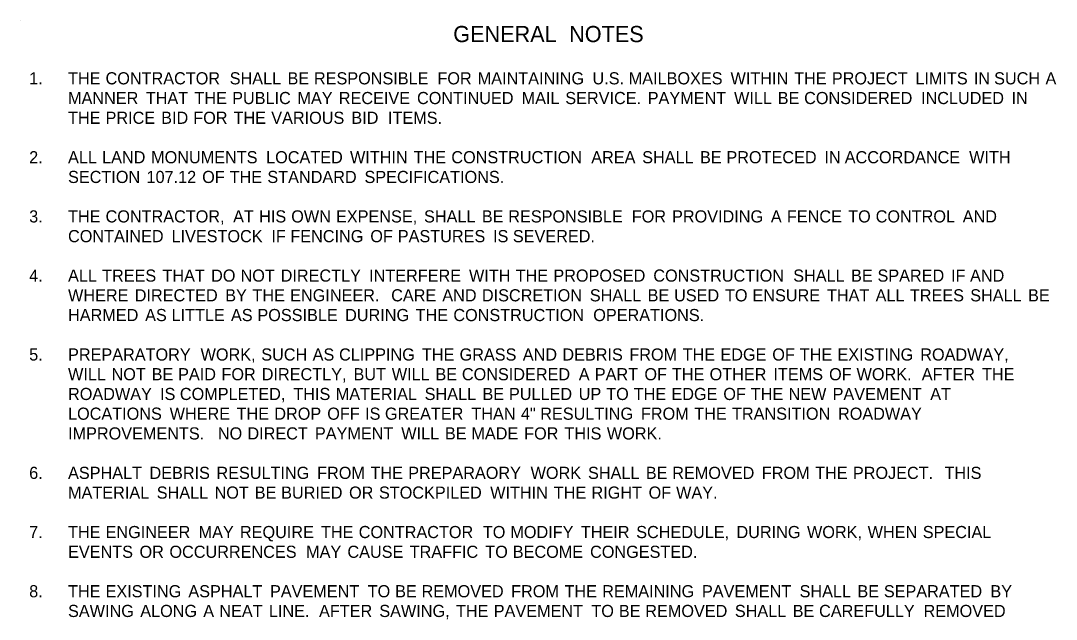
# Model space of a CAD drawing. Extents: x 1930579 to 1932219, y 596452 to 599493.
# Drawn here: x 1930766 to 1931329, y 599100 to 599425 of the extents above; entities that cross this region are included whole.
import ezdxf

# ---------------------------------------------------------------- set-up
doc = ezdxf.new("R2010")
doc.units = 0
doc.layers.add('Default', color=7, linetype='Continuous')
doc.layers.add('R_Border', color=7, linetype='Continuous')

msp = doc.modelspace()

# ---------------------------------------------------------------- linework, layer by layer
at = {"layer": 'R_Border'}
msp.add_line((1930766.07, 599425.04), (1930766.07, 599425.04), dxfattribs=at)

# ---------------------------------------------------------------- texts
at = {"layer": 'Default'}
for s, height, p in [('GENERAL', 8.8, (1931001.3, 599413.4)), (' NOTES', 8.8, (1931061.06, 599413.4)), ('1.', 6.6, (1930770.67, 599390.43)), ('THE', 6.6, (1930791.81, 599390.43)), (' CONTRACTOR', 6.6, (1930809.76, 599390.43)), (' SHALL', 6.6, (1930877.27, 599390.43)), (' BE', 6.6, (1930908.72, 599390.43)), (' RESPONSIBLE', 6.6, (1930923.09, 599390.43)), (' FOR', 6.6, (1930990.25, 599390.43)), (' MAINTAINING', 6.6, (1931012.15, 599390.43)), (' U.S.', 6.6, (1931074.59, 599390.43)), (' MAILBOXES', 6.6, (1931094.28, 599390.43)), (' WITHIN', 6.6, (1931149.66, 599390.43)), (' THE', 6.6, (1931184.25, 599390.43)), (' PROJECT', 6.6, (1931204.76, 599390.43)), (' LIMITS', 6.6, (1931250.18, 599390.43)), (' IN', 6.6, (1931281.97, 599390.43)), (' SUCH', 6.6, (1931293, 599390.43)), (' A', 6.6, (1931320.95, 599390.43)), ('MANNER', 6.6, (1930791.81, 599379.71)), (' THAT', 6.6, (1930831.65, 599379.71)), (' THE', 6.6, (1930858.1, 599379.71)), (' PUBLIC', 6.6, (1930878.62, 599379.71)), (' MAY', 6.6, (1930914.12, 599379.71)), (' RECEIVE', 6.6, (1930936.6, 599379.71)), (' CONTINUED', 6.6, (1930979.16, 599379.71)), (' MAIL', 6.6, (1931036.05, 599379.71)), (' SERVICE.', 6.6, (1931059.8, 599379.71)), (' PAYMENT', 6.6, (1931104.61, 599379.71)), (' WILL', 6.6, (1931151.57, 599379.71)), (' BE', 6.6, (1931175.32, 599379.71)), (' CONSIDERED', 6.6, (1931189.69, 599379.71)), (' INCLUDED', 6.6, (1931253.25, 599379.71)), (' IN', 6.6, (1931302.46, 599379.71)), ('THE', 6.6, (1930791.81, 599368.98)), (' PRICE', 6.6, (1930809.76, 599368.98)), (' BID', 6.6, (1930840.01, 599368.98)), (' FOR', 6.6, (1930857.46, 599368.98)), (' THE', 6.6, (1930879.36, 599368.98)), (' VARIOUS', 6.6, (1930899.87, 599368.98)), (' BID', 6.6, (1930943.46, 599368.98)), ('  ITEMS.', 6.6, (1930960.9, 599368.98)), ('2.', 6.6, (1930770.67, 599347.53)), ('ALL', 6.6, (1930791.81, 599347.53)), (' LAND', 6.6, (1930807.88, 599347.53)), (' MONUMENTS', 6.6, (1930834.55, 599347.53)), (' LOCATED', 6.6, (1930897.09, 599347.53)), (' WITHIN', 6.6, (1930942.71, 599347.53)), (' THE', 6.6, (1930977.3, 599347.53)), (' CONSTRUCTION', 6.6, (1930997.81, 599347.53)), (' AREA', 6.6, (1931073.91, 599347.53)), (' SHALL', 6.6, (1931101.6, 599347.53)), (' BE', 6.6, (1931133.05, 599347.53)), (' PROTECED', 6.6, (1931147.42, 599347.53)), (' IN', 6.6, (1931200.74, 599347.53)), (' ACCORDANCE', 6.6, (1931211.76, 599347.53)), (' WITH', 6.6, (1931279.42, 599347.53)), ('SECTION', 6.6, (1930791.81, 599336.81)), (' 107.12', 6.6, (1930832.05, 599336.81)), (' OF', 6.6, (1930862.31, 599336.81)), (' THE', 6.6, (1930877.26, 599336.81)), (' STANDARD', 6.6, (1930897.77, 599336.81)), (' SPECIFICATIONS.', 6.6, (1930950.57, 599336.81)), ('3.', 6.6, (1930770.67, 599315.36)), ('THE', 6.6, (1930791.81, 599315.36)), (' CONTRACTOR,', 6.6, (1930809.76, 599315.36)), (' AT', 6.6, (1930879.13, 599315.36)), (' HIS', 6.6, (1930893.29, 599315.36)), (' OWN', 6.6, (1930910.74, 599315.36)), (' EXPENSE,', 6.6, (1930935.09, 599315.36)), (' SHALL', 6.6, (1930982.96, 599315.36)), (' BE', 6.6, (1931014.41, 599315.36)), (' RESPONSIBLE', 6.6, (1931028.78, 599315.36)), (' FOR', 6.6, (1931095.95, 599315.36)), (' PROVIDING', 6.6, (1931117.85, 599315.36)), (' A', 6.6, (1931171.58, 599315.36)), (' FENCE', 6.6, (1931180.31, 599315.36)), (' TO', 6.6, (1931213.64, 599315.36)), (' CONTROL', 6.6, (1931228.59, 599315.36)), (' AND', 6.6, (1931275.92, 599315.36)), ('CONTAINED', 6.6, (1930791.81, 599304.63)), (' LIVESTOCK', 6.6, (1930845.63, 599304.63)), (' IF', 6.6, (1930899.93, 599304.63)), (' FENCING', 6.6, (1930910.27, 599304.63)), (' OF', 6.6, (1930953.75, 599304.63)), (' PASTURES', 6.6, (1930968.69, 599304.63)), (' IS', 6.6, (1931020.49, 599304.63)), (' SEVERED.', 6.6, (1931031.28, 599304.63)), ('4.', 6.6, (1930770.67, 599283.18)), ('ALL', 6.6, (1930791.81, 599283.18)), (' TREES', 6.6, (1930807.88, 599283.18)), (' THAT', 6.6, (1930840.71, 599283.18)), (' DO', 6.6, (1930867.17, 599283.18)), (' NOT', 6.6, (1930883.15, 599283.18)), (' DIRECTLY', 6.6, (1930904.99, 599283.18)), (' INTERFERE', 6.6, (1930953.09, 599283.18)), (' WITH', 6.6, (1931007.42, 599283.18)), (' THE', 6.6, (1931032.8, 599283.18)), (' PROPOSED', 6.6, (1931053.31, 599283.18)), (' CONSTRUCTION', 6.6, (1931107.66, 599283.18)), (' SHALL', 6.6, (1931183.75, 599283.18)), (' BE', 6.6, (1931215.2, 599283.18)), (' SPARED', 6.6, (1931229.58, 599283.18)), (' IF', 6.6, (1931269.57, 599283.18)), (' AND', 6.6, (1931279.91, 599283.18)), ('WHERE', 6.6, (1930791.81, 599272.46)), (' DIRECTED', 6.6, (1930825.64, 599272.46)), (' BY', 6.6, (1930874.85, 599272.46)), (' THE', 6.6, (1930889.65, 599272.46)), (' ENGINEER.', 6.6, (1930910.16, 599272.46)), ('  CARE', 6.6, (1930962.65, 599272.46)), (' AND', 6.6, (1930992.9, 599272.46)), (' DISCRETION', 6.6, (1931014.44, 599272.46)), (' SHALL', 6.6, (1931073.12, 599272.46)), (' BE', 6.6, (1931104.57, 599272.46)), (' USED', 6.6, (1931118.95, 599272.46)), (' TO', 6.6, (1931146.64, 599272.46)), (' ENSURE', 6.6, (1931161.59, 599272.46)), (' THAT', 6.6, (1931202.1, 599272.46)), (' ALL', 6.6, (1931228.55, 599272.46)), (' TREES', 6.6, (1931247.19, 599272.46)), (' SHALL', 6.6, (1931280.02, 599272.46)), (' BE', 6.6, (1931311.47, 599272.46)), ('HARMED', 6.6, (1930791.81, 599261.73)), (' AS', 6.6, (1930831.28, 599261.73)), (' LITTLE', 6.6, (1930845.66, 599261.73)), (' AS', 6.6, (1930877.96, 599261.73)), (' POSSIBLE', 6.6, (1930892.35, 599261.73)), (' DURING', 6.6, (1930940.04, 599261.73)), (' THE', 6.6, (1930978.39, 599261.73)), (' CONSTRUCTION', 6.6, (1930998.91, 599261.73)), (' OPERATIONS.', 6.6, (1931075, 599261.73)), ('5.', 6.6, (1930770.67, 599240.28)), ('PREPARATORY', 6.6, (1930791.81, 599240.28)), (' WORK,', 6.6, (1930861.44, 599240.28)), (' SUCH', 6.6, (1930894.43, 599240.28)), (' AS', 6.6, (1930922.38, 599240.28)), (' CLIPPING', 6.6, (1930936.76, 599240.28)), (' THE', 6.6, (1930981.79, 599240.28)), (' GRASS', 6.6, (1931002.3, 599240.28)), (' AND', 6.6, (1931036.67, 599240.28)), (' DEBRIS', 6.6, (1931058.21, 599240.28)), (' FROM', 6.6, (1931094.63, 599240.28)), (' THE', 6.6, (1931123.64, 599240.28)), (' EDGE', 6.6, (1931144.16, 599240.28)), (' OF', 6.6, (1931172.36, 599240.28)), (' THE', 6.6, (1931187.31, 599240.28)), (' EXISTING', 6.6, (1931207.82, 599240.28)), (' ROADWAY,', 6.6, (1931252.85, 599240.28)), ('WILL', 6.6, (1930791.81, 599229.56)), (' NOT', 6.6, (1930813, 599229.56)), (' BE', 6.6, (1930834.84, 599229.56)), (' PAID', 6.6, (1930849.21, 599229.56)), (' FOR', 6.6, (1930872.8, 599229.56)), (' DIRECTLY,', 6.6, (1930894.71, 599229.56)), (' BUT', 6.6, (1930944.61, 599229.56)), (' WILL', 6.6, (1930965.43, 599229.56)), (' BE', 6.6, (1930989.18, 599229.56)), (' CONSIDERED', 6.6, (1931003.56, 599229.56)), (' A', 6.6, (1931067.12, 599229.56)), (' PART', 6.6, (1931075.84, 599229.56)), (' OF', 6.6, (1931102.82, 599229.56)), (' THE', 6.6, (1931117.76, 599229.56)), (' OTHER', 6.6, (1931138.28, 599229.56)), (' ITEMS', 6.6, (1931172.99, 599229.56)), (' OF', 6.6, (1931203.25, 599229.56)), (' WORK.', 6.6, (1931218.2, 599229.56)), ('  AFTER', 6.6, (1931251.2, 599229.56)), (' THE', 6.6, (1931286.43, 599229.56)), ('ROADWAY', 6.6, (1930791.81, 599218.83)), (' IS', 6.6, (1930839.39, 599218.83)), (' COMPLETED,', 6.6, (1930850.18, 599218.83)), (' THIS', 6.6, (1930911.88, 599218.83)), (' MATERIAL', 6.6, (1930934.96, 599218.83)), (' SHALL', 6.6, (1930983.31, 599218.83)), (' BE', 6.6, (1931014.76, 599218.83)), (' PULLED', 6.6, (1931029.14, 599218.83)), (' UP', 6.6, (1931067.08, 599218.83)), (' TO', 6.6, (1931082.05, 599218.83)), (' THE', 6.6, (1931097.01, 599218.83)), (' EDGE', 6.6, (1931117.52, 599218.83)), (' OF', 6.6, (1931145.73, 599218.83)), (' THE', 6.6, (1931160.67, 599218.83)), (' NEW', 6.6, (1931181.19, 599218.83)), (' PAVEMENT', 6.6, (1931205.16, 599218.83)), (' AT', 6.6, (1931258.27, 599218.83)), ('LOCATIONS', 6.6, (1930791.81, 599208.11)), (' WHERE', 6.6, (1930844.62, 599208.11)), (' THE', 6.6, (1930881.01, 599208.11)), (' DROP', 6.6, (1930901.53, 599208.11)), (' OFF', 6.6, (1930930.33, 599208.11)), (' IS', 6.6, (1930950.91, 599208.11)), (' GREATER', 6.6, (1930961.7, 599208.11)), (' THAN', 6.6, (1931008.72, 599208.11)), (' 4"', 6.6, (1931035.64, 599208.11)), (' RESULTING', 6.6, (1931046.16, 599208.11)), (' FROM', 6.6, (1931100.93, 599208.11)), (' THE', 6.6, (1931129.94, 599208.11)), (' TRANSITION', 6.6, (1931150.46, 599208.11)), (' ROADWAY', 6.6, (1931208.11, 599208.11)), ('IMPROVEMENTS.', 6.6, (1930791.81, 599197.38)), ('  NO', 6.6, (1930868.38, 599197.38)), (' DIRECT', 6.6, (1930886.92, 599197.38)), (' PAYMENT', 6.6, (1930923.62, 599197.38)), (' WILL', 6.6, (1930970.58, 599197.38)), (' BE', 6.6, (1930994.33, 599197.38)), (' MADE', 6.6, (1931008.7, 599197.38)), (' FOR', 6.6, (1931037.42, 599197.38)), (' THIS', 6.6, (1931059.32, 599197.38)), (' WORK.', 6.6, (1931082.4, 599197.38)), ('6.', 6.6, (1930770.67, 599175.93)), ('ASPHALT', 6.6, (1930791.81, 599175.93)), (' DEBRIS', 6.6, (1930833.65, 599175.93)), (' RESULTING', 6.6, (1930870.07, 599175.93)), (' FROM', 6.6, (1930924.83, 599175.93)), (' THE', 6.6, (1930953.84, 599175.93)), (' PREPARAORY', 6.6, (1930974.36, 599175.93)), (' WORK', 6.6, (1931040.92, 599175.93)), (' SHALL', 6.6, (1931072.15, 599175.93)), (' BE', 6.6, (1931103.6, 599175.93)), (' REMOVED', 6.6, (1931117.97, 599175.93)), (' FROM', 6.6, (1931166.67, 599175.93)), (' THE', 6.6, (1931195.69, 599175.93)), (' PROJECT.', 6.6, (1931216.2, 599175.93)), ('  THIS', 6.6, (1931263.56, 599175.93)), ('MATERIAL', 6.6, (1930791.81, 599165.21)), (' SHALL', 6.6, (1930837.6, 599165.21)), (' NOT', 6.6, (1930869.05, 599165.21)), (' BE', 6.6, (1930890.89, 599165.21)), (' BURIED', 6.6, (1930905.26, 599165.21)), (' OR', 6.6, (1930942.18, 599165.21)), (' STOCKPILED', 6.6, (1930958.45, 599165.21)), (' WITHIN', 6.6, (1931018.94, 599165.21)), (' THE', 6.6, (1931053.52, 599165.21)), (' RIGHT', 6.6, (1931074.04, 599165.21)), (' OF', 6.6, (1931105.1, 599165.21)), (' WAY.', 6.6, (1931120.05, 599165.21)), ('7.', 6.6, (1930770.67, 599143.76)), ('THE', 6.6, (1930791.81, 599143.76)), (' ENGINEER', 6.6, (1930809.76, 599143.76)), (' MAY', 6.6, (1930860.37, 599143.76)), (' REQUIRE', 6.6, (1930882.84, 599143.76)), (' THE', 6.6, (1930926.93, 599143.76)), (' CONTRACTOR', 6.6, (1930947.45, 599143.76)), (' TO', 6.6, (1931014.95, 599143.76)), (' MODIFY', 6.6, (1931029.91, 599143.76)), (' THEIR', 6.6, (1931068.26, 599143.76)), (' SCHEDULE,', 6.6, (1931098.36, 599143.76)), (' DURING', 6.6, (1931152.89, 599143.76)), (' WORK,', 6.6, (1931191.24, 599143.76)), (' WHEN', 6.6, (1931224.23, 599143.76)), (' SPECIAL', 6.6, (1931254.21, 599143.76)), ('EVENTS', 6.6, (1930791.81, 599133.03)), (' OR', 6.6, (1930828.23, 599133.03)), (' OCCURRENCES', 6.6, (1930844.5, 599133.03)), (' MAY', 6.6, (1930918.83, 599133.03)), (' CAUSE', 6.6, (1930941.3, 599133.03)), (' TRAFFIC', 6.6, (1930975.15, 599133.03)), (' TO', 6.6, (1931016.28, 599133.03)), (' BECOME', 6.6, (1931031.23, 599133.03)), (' CONGESTED.', 6.6, (1931073.27, 599133.03)), ('8.', 6.6, (1930770.67, 599111.58)), ('THE', 6.6, (1930791.81, 599111.58)), (' EXISTING', 6.6, (1930809.76, 599111.58)), (' ASPHALT', 6.6, (1930854.79, 599111.58)), (' PAVEMENT', 6.6, (1930899.19, 599111.58)), (' TO', 6.6, (1930952.31, 599111.58)), (' BE', 6.6, (1930967.26, 599111.58)), (' REMOVED', 6.6, (1930981.63, 599111.58)), (' FROM', 6.6, (1931030.33, 599111.58)), (' THE', 6.6, (1931059.35, 599111.58)), (' REMAINING', 6.6, (1931079.86, 599111.58)), (' PAVEMENT', 6.6, (1931134.11, 599111.58)), (' SHALL', 6.6, (1931187.22, 599111.58)), (' BE', 6.6, (1931218.67, 599111.58)), (' SEPARATED', 6.6, (1931233.04, 599111.58)), (' BY', 6.6, (1931290.98, 599111.58)), ('SAWING', 6.6, (1930791.81, 599100.86)), (' ALONG', 6.6, (1930828.63, 599100.86)), (' A', 6.6, (1930862.9, 599100.86)), (' NEAT', 6.6, (1930871.63, 599100.86)), (' LINE.', 6.6, (1930898.6, 599100.86)), ('  AFTER', 6.6, (1930923.41, 599100.86)), (' SAWING,', 6.6, (1930958.64, 599100.86)), (' THE', 6.6, (1931000.35, 599100.86)), (' PAVEMENT', 6.6, (1931020.86, 599100.86)), (' TO', 6.6, (1931073.97, 599100.86)), (' BE', 6.6, (1931088.93, 599100.86)), (' REMOVED', 6.6, (1931103.3, 599100.86)), (' SHALL', 6.6, (1931152, 599100.86)), (' BE', 6.6, (1931183.45, 599100.86)), (' CAREFULLY', 6.6, (1931197.82, 599100.86)), (' REMOVED', 6.6, (1931254.64, 599100.86))]:
    msp.add_text(s, height=height, dxfattribs=at).set_placement(p)

doc.saveas('drawing.dxf')
